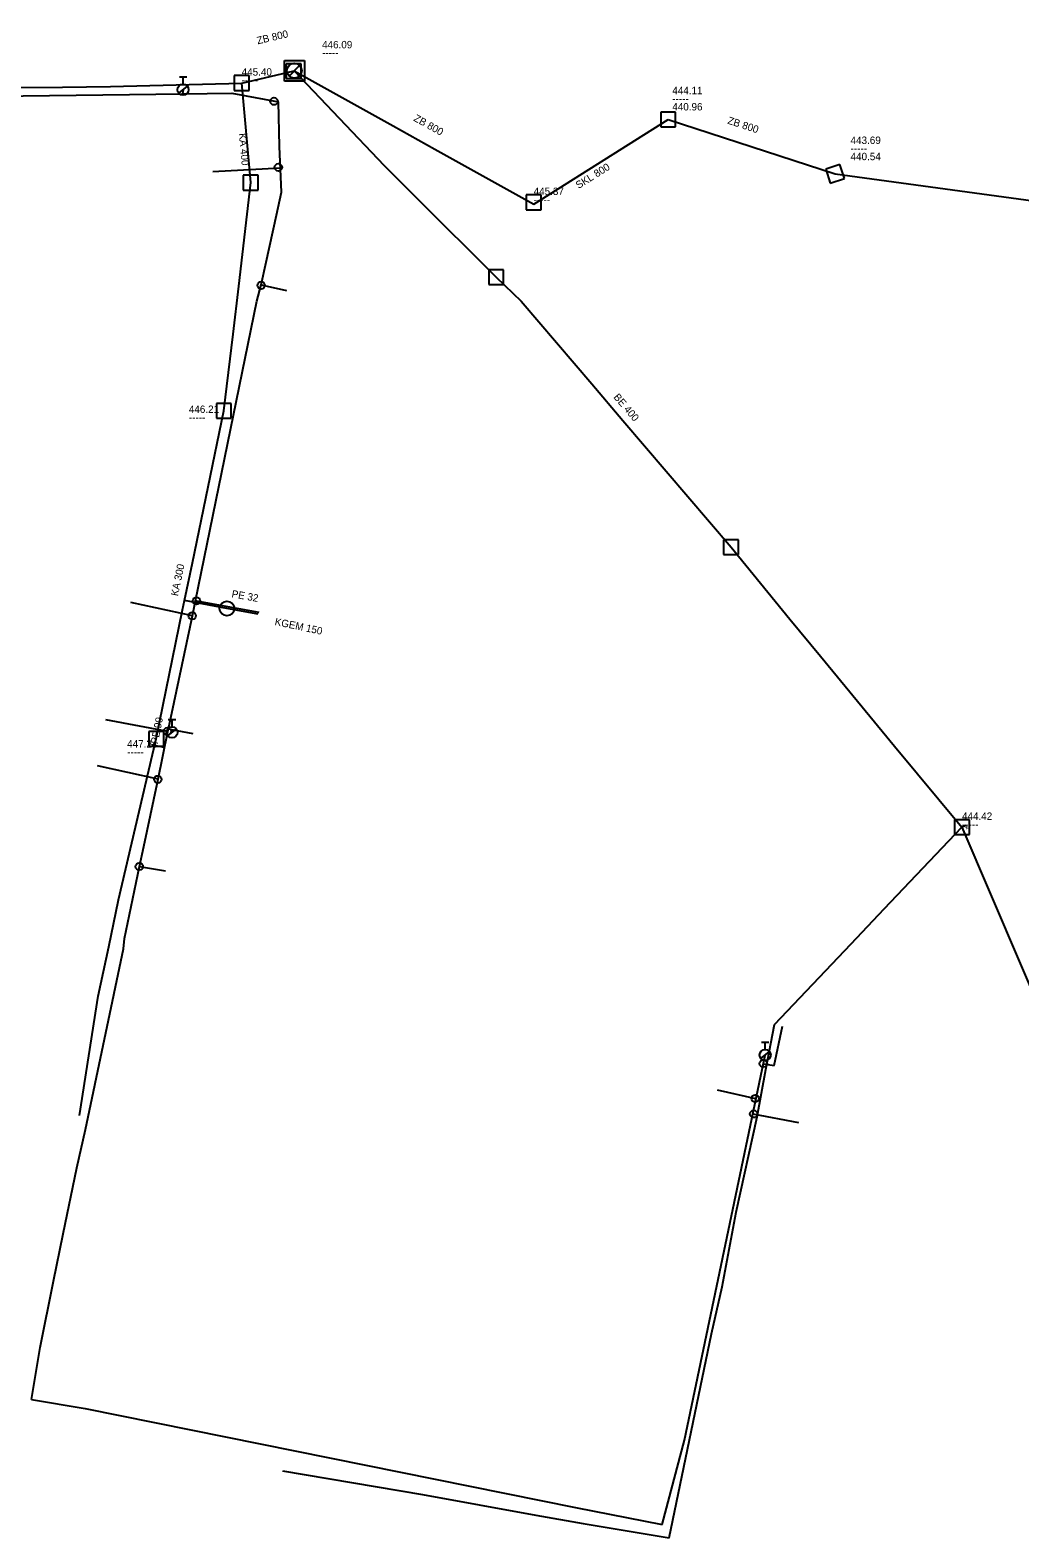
# Model space of a CAD drawing. Extents: x -756595 to -756146, y -1112266 to -1111946.
# Drawn here: x -756468 to -756334.1, y -1112202.5 to -1111998.5 of the extents above; entities that cross this region are included whole.
import ezdxf

# ---------------------------------------------------------------- set-up
doc = ezdxf.new("R2010")
doc.units = 0
doc.layers.add('Level 0', color=7, linetype='Continuous')

msp = doc.modelspace()

# ---------------------------------------------------------------- linework, layer by layer
at = {"layer": 'Level 0'}
for p, q in [((-756433.62, -1112002.6), (-756430.92, -1112002.6)), ((-756433.62, -1112005.41), (-756433.62, -1112002.6)), ((-756431.37, -1112003.03), (-756433.37, -1112003.03)), ((-756433.37, -1112003.03), (-756433.37, -1112005.03)), ((-756432.978, -1112004.69), (-756431.572, -1112003.286)), ((-756431.37, -1112005.03), (-756431.37, -1112003.03)), ((-756430.92, -1112002.6), (-756430.92, -1112005.41)), ((-756447.84, -1112004.79), (-756446.84, -1112004.79)), ((-756447.34, -1112005.79), (-756447.34, -1112004.79)), ((-756438.41, -1112004.64), (-756440.41, -1112004.64)), ((-756440.41, -1112004.64), (-756440.41, -1112006.64)), ((-756439.41, -1112005.64), (-756432.29, -1112003.97)), ((-756438.41, -1112006.64), (-756438.41, -1112004.64)), ((-756433.37, -1112005.03), (-756431.37, -1112005.03)), ((-756432.29, -1112003.97), (-756420.13, -1112016.81)), ((-756432.29, -1112003.97), (-756418.93, -1112011.42)), ((-756483.65, -1112007.57), (-756447.44, -1112007.09)), ((-756481.33, -1112006.32), (-756463.65, -1112006.21)), ((-756463.65, -1112006.21), (-756457.15, -1112006.1)), ((-756457.15, -1112006.1), (-756439.41, -1112005.64)), ((-756447.928, -1112007.002), (-756446.748, -1112006.076)), ((-756447.34, -1112006.54), (-756447.44, -1112007.09)), ((-756447.44, -1112007.09), (-756440.73, -1112007.02)), ((-756440.73, -1112007.02), (-756434.44, -1112008.17)), ((-756440.41, -1112006.64), (-756438.41, -1112006.64)), ((-756438.19, -1112019.12), (-756439.41, -1112005.64)), ((-756430.92, -1112005.41), (-756433.62, -1112005.41)), ((-756434.31, -1112014.23), (-756434.44, -1112008.17)), ((-756418.93, -1112011.42), (-756413.25, -1112014.58)), ((-756399.89, -1112022.03), (-756381.7, -1112010.59)), ((-756380.7, -1112009.59), (-756382.7, -1112009.59)), ((-756382.7, -1112009.59), (-756382.7, -1112011.59)), ((-756381.7, -1112010.59), (-756359.1, -1112017.93)), ((-756380.7, -1112011.59), (-756380.7, -1112009.59)), ((-756382.7, -1112011.59), (-756380.7, -1112011.59)), ((-756434.01, -1112020.43), (-756434.31, -1112014.23)), ((-756413.25, -1112014.58), (-756399.89, -1112022.03)), ((-756434.17, -1112017.16), (-756443.33, -1112017.64)), ((-756420.13, -1112016.81), (-756415.75, -1112021.16)), ((-756358.458, -1112016.67), (-756360.36, -1112017.288)), ((-756360.36, -1112017.288), (-756359.742, -1112019.19)), ((-756357.84, -1112018.572), (-756358.458, -1112016.67)), ((-756439.8, -1112033.15), (-756438.19, -1112019.12)), ((-756437.19, -1112018.12), (-756439.19, -1112018.12)), ((-756439.19, -1112018.12), (-756439.19, -1112020.12)), ((-756437.19, -1112020.12), (-756437.19, -1112018.12)), ((-756359.742, -1112019.19), (-756357.84, -1112018.572)), ((-756359.1, -1112017.93), (-756330.28, -1112021.87)), ((-756439.19, -1112020.12), (-756437.19, -1112020.12)), ((-756434.69, -1112023.53), (-756434.01, -1112020.43)), ((-756415.75, -1112021.16), (-756404.96, -1112031.9)), ((-756398.89, -1112020.79), (-756400.89, -1112020.79)), ((-756400.89, -1112020.79), (-756400.89, -1112022.79)), ((-756398.89, -1112022.79), (-756398.89, -1112020.79)), ((-756436.08, -1112029.88), (-756434.69, -1112023.53)), ((-756400.89, -1112022.79), (-756398.89, -1112022.79)), ((-756436.76, -1112032.97), (-756436.08, -1112029.88)), ((-756403.96, -1112030.9), (-756405.96, -1112030.9)), ((-756405.96, -1112030.9), (-756405.96, -1112032.9)), ((-756404.96, -1112031.9), (-756401.58, -1112035.15)), ((-756403.96, -1112032.9), (-756403.96, -1112030.9)), ((-756440.56, -1112039.61), (-756439.8, -1112033.15)), ((-756437.38, -1112035.18), (-756436.76, -1112032.97)), ((-756436.76, -1112032.97), (-756433.34, -1112033.72)), ((-756405.96, -1112032.9), (-756403.96, -1112032.9)), ((-756445.65, -1112075.69), (-756437.38, -1112035.18)), ((-756401.58, -1112035.15), (-756392.02, -1112046.36)), ((-756441.82, -1112049.99), (-756440.56, -1112039.61)), ((-756392.02, -1112046.36), (-756387.81, -1112051.3)), ((-756446.09, -1112070.58), (-756441.82, -1112049.99)), ((-756440.82, -1112048.99), (-756442.82, -1112048.99)), ((-756442.82, -1112048.99), (-756442.82, -1112050.99)), ((-756440.82, -1112050.99), (-756440.82, -1112048.99)), ((-756442.82, -1112050.99), (-756440.82, -1112050.99)), ((-756387.81, -1112051.3), (-756373.18, -1112068.46)), ((-756372.18, -1112067.46), (-756374.18, -1112067.46)), ((-756374.18, -1112067.46), (-756374.18, -1112069.46)), ((-756373.18, -1112068.46), (-756365.2, -1112078.18)), ((-756372.18, -1112069.46), (-756372.18, -1112067.46)), ((-756447.13, -1112075.67), (-756446.09, -1112070.58)), ((-756374.18, -1112069.46), (-756372.18, -1112069.46)), ((-756446.07, -1112077.75), (-756454.43, -1112075.95)), ((-756447.4, -1112076.95), (-756447.13, -1112075.67)), ((-756441.4, -1112076.75), (-756447.13, -1112075.67)), ((-756446.07, -1112077.75), (-756445.65, -1112075.69)), ((-756445.65, -1112075.69), (-756445.53, -1112075.71)), ((-756445.53, -1112075.71), (-756437.09, -1112077.23)), ((-756437.16, -1112077.53), (-756441.4, -1112076.75)), ((-756450.97, -1112094.38), (-756447.4, -1112076.95)), ((-756449.31, -1112093.01), (-756446.07, -1112077.75)), ((-756365.2, -1112078.18), (-756361.07, -1112083.2)), ((-756361.07, -1112083.2), (-756351.05, -1112095.39)), ((-756449.39, -1112093.38), (-756457.78, -1112091.82)), ((-756449.428, -1112093.972), (-756448.248, -1112093.046)), ((-756449.39, -1112093.38), (-756449.31, -1112093.01)), ((-756449.34, -1112091.76), (-756448.34, -1112091.76)), ((-756449.31, -1112093.01), (-756448.92, -1112093.1)), ((-756448.92, -1112093.1), (-756446.01, -1112093.65)), ((-756448.84, -1112092.76), (-756448.84, -1112091.76)), ((-756456.07, -1112116.16), (-756450.97, -1112094.38)), ((-756449.97, -1112093.38), (-756451.97, -1112093.38)), ((-756451.97, -1112093.38), (-756451.97, -1112095.38)), ((-756450.7, -1112099.86), (-756449.39, -1112093.38)), ((-756449.97, -1112095.38), (-756449.97, -1112093.38)), ((-756451.97, -1112095.38), (-756449.97, -1112095.38)), ((-756450.31, -1112095.43), (-756449.83, -1112095.54)), ((-756351.05, -1112095.39), (-756341.92, -1112106.35)), ((-756450.7, -1112099.86), (-756458.93, -1112098.02)), ((-756451.28, -1112102.59), (-756450.7, -1112099.86)), ((-756452.65, -1112108.94), (-756451.28, -1112102.59)), ((-756340.92, -1112105.35), (-756342.92, -1112105.35)), ((-756342.92, -1112105.35), (-756342.92, -1112107.35)), ((-756340.92, -1112107.35), (-756340.92, -1112105.35)), ((-756352.45, -1112117.39), (-756341.92, -1112106.35)), ((-756342.92, -1112107.35), (-756340.92, -1112107.35)), ((-756341.35, -1112106.12), (-756341.92, -1112106.35)), ((-756341.92, -1112106.35), (-756330.05, -1112134.17)), ((-756453.23, -1112111.67), (-756452.65, -1112108.94)), ((-756455.27, -1112121.42), (-756453.23, -1112111.67)), ((-756453.23, -1112111.67), (-756449.71, -1112112.24)), ((-756457.41, -1112122.52), (-756456.07, -1112116.16)), ((-756356.92, -1112122.11), (-756352.45, -1112117.39)), ((-756455.41, -1112122.81), (-756455.27, -1112121.42)), ((-756460.54, -1112147.24), (-756455.41, -1112122.81)), ((-756458.82, -1112129.2), (-756457.41, -1112122.52)), ((-756367.28, -1112133.04), (-756356.92, -1112122.11)), ((-756461.36, -1112145.37), (-756458.82, -1112129.2)), ((-756368.45, -1112139.14), (-756367.28, -1112133.04)), ((-756367.36, -1112138.61), (-756366.22, -1112133.25)), ((-756369.06, -1112135.43), (-756368.06, -1112135.43)), ((-756368.56, -1112136.43), (-756368.56, -1112135.43)), ((-756379.46, -1112189.27), (-756368.56, -1112137.18)), ((-756369.148, -1112137.642), (-756367.968, -1112136.716)), ((-756369.66, -1112145.53), (-756368.45, -1112139.14)), ((-756368.8, -1112138.35), (-756367.36, -1112138.61)), ((-756369.8, -1112143.09), (-756375, -1112141.91)), ((-756372.47, -1112158.44), (-756369.66, -1112145.53)), ((-756370.22, -1112145.12), (-756364.05, -1112146.32)), ((-756461.73, -1112152.42), (-756460.54, -1112147.24)), ((-756463.56, -1112161.39), (-756461.73, -1112152.42)), ((-756374.39, -1112168.55), (-756372.47, -1112158.44)), ((-756464.86, -1112167.76), (-756463.56, -1112161.39)), ((-756466.69, -1112176.73), (-756464.86, -1112167.76)), ((-756375.83, -1112174.89), (-756374.39, -1112168.55)), ((-756467.84, -1112183.77), (-756466.69, -1112176.73)), ((-756381.53, -1112202.51), (-756375.83, -1112174.89)), ((-756467.84, -1112183.77), (-756460.6, -1112185.01)), ((-756460.6, -1112185.01), (-756394.23, -1112198.42)), ((-756382.5, -1112200.7), (-756379.46, -1112189.27)), ((-756433.87, -1112193.42), (-756414.93, -1112196.63)), ((-756414.93, -1112196.63), (-756399.59, -1112199.43)), ((-756394.23, -1112198.42), (-756382.5, -1112200.7)), ((-756399.59, -1112199.43), (-756393.19, -1112200.55)), ((-756393.19, -1112200.55), (-756381.53, -1112202.51))]:
    msp.add_line(p, q, dxfattribs=at)
for centre, radius in [((-756432.29, -1112003.97), 1), ((-756447.34, -1112006.54), 0.75), ((-756435.04, -1112008.11), 0.5), ((-756434.45, -1112017.05), 0.5), ((-756436.78, -1112033.02), 0.5), ((-756445.53, -1112075.71), 0.5), ((-756441.4, -1112076.75), 1), ((-756446.1, -1112077.73), 0.5), ((-756449.47, -1112093.37), 0.5), ((-756448.84, -1112093.51), 0.75), ((-756450.75, -1112099.87), 0.5), ((-756453.27, -1112111.67), 0.5), ((-756368.56, -1112137.18), 0.75), ((-756368.81, -1112138.33), 0.5), ((-756369.91, -1112143.05), 0.5), ((-756370.12, -1112145.15), 0.5)]:
    msp.add_circle(centre, radius, dxfattribs=at)

# ---------------------------------------------------------------- texts
for s, rotation, p in [('ZB 800', 13.2, (-756437.24, -1112000.41)), ('ZB 800', 330.911, (-756416.23, -1112010.7)), ('ZB 800', 342.007, (-756373.74, -1112011.12)), ('KA 400', 275.171, (-756439.8, -1112012.47)), ('SKL 800', 32.166, (-756393.81, -1112019.99)), ('BE 400', 310.439, (-756389.15, -1112048.18)), ('KA 300', 78.089, (-756448.04, -1112075.13)), ('PE 32', 349.791, (-756440.83, -1112075.22)), ('KGEM 150', 348.17, (-756435, -1112078.97)), ('lPE 90', 78.571, (-756450.83, -1112095.44)), ('*', 21.975, (-756341.26, -1112107.16))]:
    msp.add_text(s, height=1, rotation=rotation, dxfattribs=at).set_placement(p)
for s, p in [('446.09', (-756428.53, -1112000.94)), ('-----', (-756428.53, -1112002.04)), ('445.40', (-756439.41, -1112004.64)), ('-----', (-756439.41, -1112005.74)), ('444.11', (-756381.13, -1112007.15)), ('440.96', (-756381.13, -1112009.35)), ('-----', (-756381.13, -1112008.25)), ('443.69', (-756357, -1112013.88)), ('440.54', (-756357, -1112016.08)), ('-----', (-756357, -1112014.98)), ('445.37', (-756399.89, -1112020.79)), ('-----', (-756399.89, -1112021.89)), ('446.21', (-756446.56, -1112050.28)), ('-----', (-756446.56, -1112051.38)), ('447.24', (-756454.91, -1112095.56)), ('-----', (-756454.91, -1112096.66)), ('444.42', (-756341.92, -1112105.35)), ('-----', (-756341.92, -1112106.45))]:
    msp.add_text(s, height=1, dxfattribs=at).set_placement(p)

doc.saveas('drawing.dxf')
